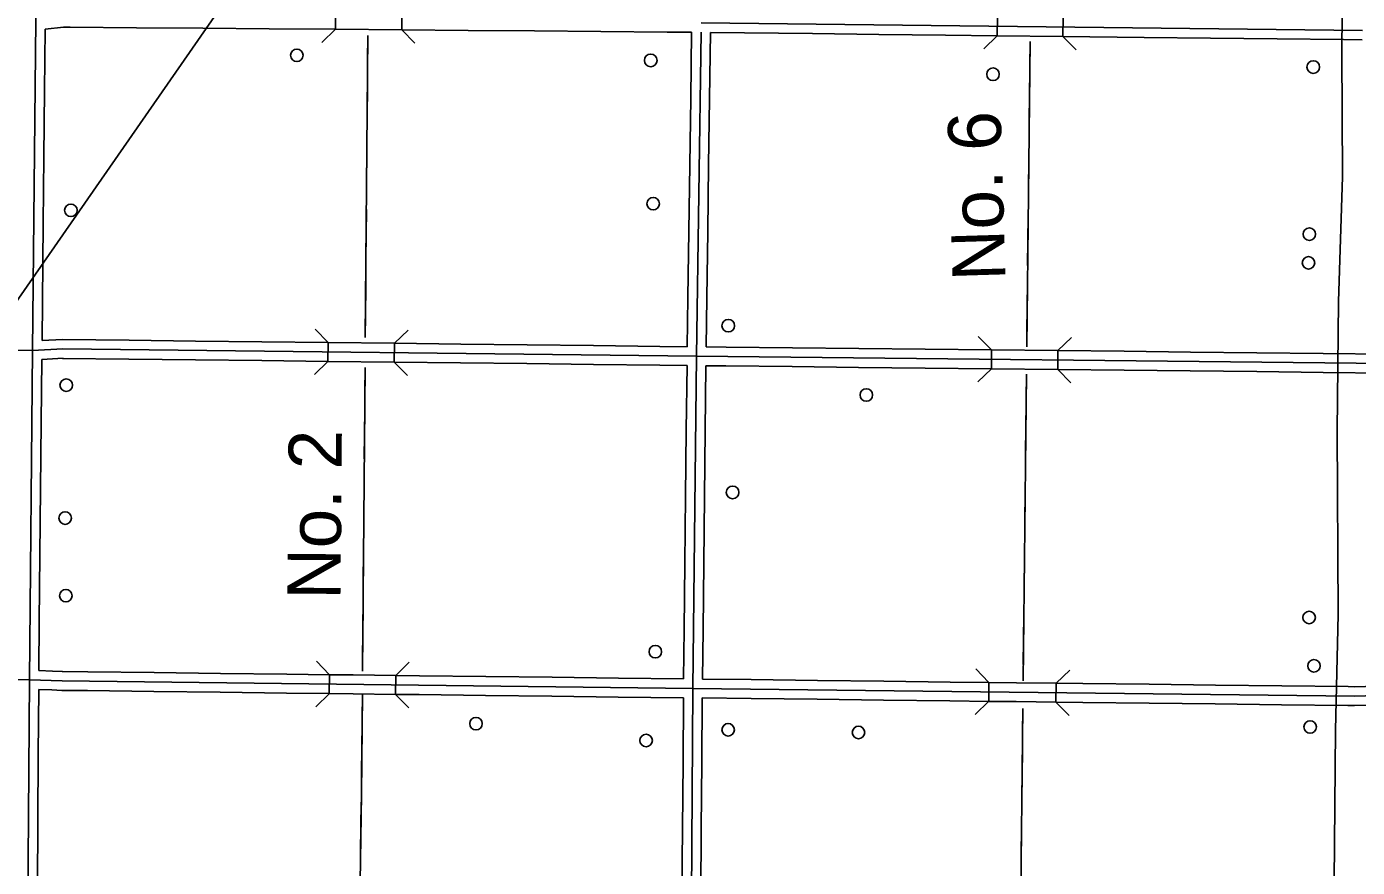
# Model space of a CAD drawing. Extents: x -4306 to 3843, y 131 to 8341.
# Drawn here: x -1949 to -255, y 879 to 1950 of the extents above; entities that cross this region are included whole.
import ezdxf

# ---------------------------------------------------------------- set-up
doc = ezdxf.new("R2010")
doc.units = 0
for name, color, linetype in [('10', 7, 'Continuous'), ('31', 7, 'Continuous'), ('32', 7, 'Continuous'), ('38', 7, 'Continuous'), ('50', 7, 'Continuous'), ('56', 7, 'Continuous'), ('57', 7, 'Continuous')]:
    doc.layers.add(name, color=color, linetype=linetype)

msp = doc.modelspace()

# ---------------------------------------------------------------- linework, layer by layer
at = {"layer": '10'}
msp.add_lwpolyline([(-314.4, 293.8), (-314.5, 305.1), (-312.3, 441.3), (-305.4, 600.9), (-302, 628.3), (-293.8, 664.7), (-283.6, 735.2), (-284.1, 861.9), (-282.2, 1054.1), (-278.9, 1201.3), (-280.3, 1434.8), (-278.7, 1599.9), (-273.4, 1758.6), (-274.2, 1917.6), (-271, 2305.4), (-270.3, 2716.6), (-269.9, 2753.7)], dxfattribs=at)
at = {"layer": '31'}
for p, q in [((-713.1, 1938.1), (-712.8, 1962.1)), ((-629.6, 1937.2), (-629.3, 1961.2)), ((-948.3, 1940.8), (-1078.4, 1942.2)), ((-713.1, 1938.1), (-779.3, 1938.9)), ((-629.6, 1937.2), (-713.1, 1938.1)), ((-525.9, 1936), (-629.6, 1937.2)), ((-441.4, 1935.1), (-525.9, 1936)), ((-356.9, 1934.1), (-441.4, 1935.1)), ((-272.4, 1933.2), (-356.9, 1934.1)), ((-248.5, 1932.9), (-272.4, 1933.2)), ((-1926.5, 1868.2), (-1927.3, 1783.7)), ((-1927.3, 1783.7), (-1928.2, 1699.2)), ((-1929.7, 1549.9), (-1928.2, 1699.2)), ((-1928.2, 1699.2), (-1928.2, 1699.2)), ((-1930, 1525.9), (-1930.7, 1445.7)), ((-1930.7, 1445.7), (-1931.5, 1361.3)), ((-1931.5, 1361.3), (-1931.5, 1361.3)), ((-1933.2, 1192.3), (-1933.8, 1129.8)), ((-1934, 1105.8), (-1934.5, 1023.3))]:
    msp.add_line(p, q, dxfattribs=at)
for points in [[(-1925.7, 1946.5), (-1926.5, 1868.2)], [(-948.3, 1940.8), (-863.8, 1939.8)], [(-863.8, 1939.8), (-779.3, 1938.9)], [(-1932.4, 1276.8), (-1931.5, 1361.3)], [(-1933.2, 1192.3), (-1932.4, 1276.8)], [(-1935.1, 938.9), (-1934.5, 1023.3)], [(-1935.7, 854.4), (-1935.1, 938.9)]]:
    msp.add_lwpolyline(points, dxfattribs=at)
at = {"layer": '32'}
for p, q in [((-1556.1, 1946.2), (-1555.9, 1970.2)), ((-1471.6, 1945.5), (-1471.4, 1969.5)), ((-248.2, 1944.9), (-1090.3, 1954.4)), ((-1925.7, 1946.5), (-1902.6, 1949)), ((-1902.6, 1949), (-1894, 1948.9)), ((-1894, 1948.9), (-1809.6, 1948.3)), ((-1809.6, 1948.3), (-1725.1, 1947.6)), ((-1725.1, 1947.6), (-1640.6, 1946.9)), ((-1640.6, 1946.9), (-1556.1, 1946.2)), ((-1556.1, 1946.2), (-1471.6, 1945.5)), ((-1471.6, 1945.5), (-1387.1, 1944.8)), ((-1387.1, 1944.8), (-1302.6, 1944.1)), ((-1302.6, 1944.1), (-1218.2, 1943.4)), ((-1218.2, 1943.4), (-1133.7, 1942.7)), ((-1133.7, 1942.7), (-1102.6, 1942.5)), ((-1102.4, 1942.7), (-1103.6, 1858.2)), ((-1090.4, 1942.6), (-1096.1, 1530.1)), ((-1078.4, 1942.2), (-1079.6, 1857.9)), ((-1103.6, 1858.2), (-1104.8, 1773.8)), ((-1079.6, 1857.9), (-1080.8, 1773.4)), ((-1104.8, 1773.8), (-1105.9, 1689.3)), ((-1080.8, 1773.4), (-1081.9, 1688.9)), ((-1105.9, 1689.3), (-1107.1, 1604.8)), ((-1081.9, 1688.9), (-1083.1, 1604.5)), ((-1107.1, 1604.8), (-1108, 1542.2)), ((-1083.1, 1604.5), (-1084, 1542)), ((-1929.7, 1549.9), (-1903.6, 1551.4)), ((-1903.6, 1551.4), (-1818.7, 1550.4)), ((-1818.7, 1550.4), (-1734.3, 1549.4)), ((-1734.3, 1549.4), (-1649.8, 1548.4)), ((-1649.8, 1548.4), (-1565.3, 1547.5)), ((-1565.6, 1523.5), (-1565.3, 1547.5)), ((-1565.3, 1547.5), (-1480.8, 1546.5)), ((-1481.1, 1522.5), (-1480.8, 1546.5)), ((-1480.8, 1546.5), (-1396.3, 1545.5)), ((-1396.3, 1545.5), (-1311.8, 1544.6)), ((-1311.8, 1544.6), (-1227.4, 1543.6)), ((-1227.4, 1543.6), (-1142.9, 1542.6)), ((-1142.9, 1542.6), (-1108, 1542.2)), ((-2581.2, 1542), (-1941.9, 1537.3)), ((-1941.9, 1537.3), (-1903.4, 1539.3)), ((-1930, 1525.9), (-1902.7, 1527.4)), ((-1903.5, 1527.3), (-1819, 1526.4)), ((-1903.4, 1539.3), (-1096.1, 1530.1)), ((-1819, 1526.4), (-1734.5, 1525.4)), ((-1734.5, 1525.4), (-1650, 1524.4)), ((-1096.1, 1530.1), (-1100.7, 1107.1)), ((-1096.1, 1530.1), (156, 1516.7)), ((-1084, 1542), (-1058.4, 1541.7)), ((-1058.4, 1541.7), (-973.9, 1540.8)), ((-973.9, 1540.8), (-889.4, 1539.9)), ((-889.4, 1539.9), (-804.9, 1539)), ((-804.9, 1539), (-720.5, 1538.1)), ((-720.7, 1514.1), (-720.5, 1538.1)), ((-720.5, 1538.1), (-636, 1537.2)), ((-636.2, 1513.2), (-636, 1537.2)), ((-636, 1537.2), (-551.5, 1536.3)), ((-551.5, 1536.3), (-467, 1535.4)), ((-467, 1535.4), (-382.5, 1534.4)), ((-382.5, 1534.4), (-298, 1533.5)), ((-298, 1533.5), (-213.6, 1532.6)), ((-1650, 1524.4), (-1565.6, 1523.5)), ((-1565.6, 1523.5), (-1481.1, 1522.5)), ((-1481.1, 1522.5), (-1396.6, 1521.5)), ((-1396.6, 1521.5), (-1312.1, 1520.6)), ((-1312.1, 1520.6), (-1227.6, 1519.6)), ((-1227.6, 1519.6), (-1143.1, 1518.6)), ((-1143.1, 1518.6), (-1108.3, 1518.2)), ((-1108.3, 1518.2), (-1109.2, 1435.8)), ((-1084.3, 1518), (-1085.2, 1435.5)), ((-1084.3, 1518), (-1058.7, 1517.7)), ((-1058.7, 1517.7), (-974.2, 1516.8)), ((-974.2, 1516.8), (-889.7, 1515.9)), ((-889.7, 1515.9), (-805.2, 1515)), ((-805.2, 1515), (-720.7, 1514.1)), ((-720.7, 1514.1), (-636.2, 1513.2)), ((-636.2, 1513.2), (-551.7, 1512.3)), ((-551.7, 1512.3), (-467.3, 1511.4)), ((-467.3, 1511.4), (-382.8, 1510.4)), ((-382.8, 1510.4), (-298.3, 1509.5)), ((-298.3, 1509.5), (-213.8, 1508.6)), ((-1109.2, 1435.8), (-1110.1, 1351.3)), ((-1085.2, 1435.5), (-1086.1, 1351)), ((-1110.1, 1351.3), (-1111, 1266.8)), ((-1086.1, 1351), (-1087, 1266.6)), ((-1111.9, 1182.3), (-1111, 1266.8)), ((-1111.9, 1182.3), (-1111, 1266.8)), ((-1087, 1266.6), (-1087.9, 1182.1)), ((-1111.9, 1182.3), (-1112.6, 1119.3)), ((-1087.9, 1182.1), (-1088.6, 1119)), ((-2592.6, 1124.5), (-1945.9, 1118.2)), ((-1933.8, 1129.8), (-1916.3, 1129.2)), ((-1916.3, 1129.2), (-1903.7, 1128.7)), ((-1871.4, 1128.3), (-1904, 1128.7)), ((-1786.9, 1127.3), (-1871.4, 1128.3)), ((-1702.4, 1126.3), (-1786.9, 1127.3)), ((-1617.9, 1125.3), (-1702.4, 1126.3)), ((-1563.6, 1124.6), (-1617.9, 1125.3)), ((-1563.6, 1124.6), (-1563.9, 1100.6)), ((-1533.5, 1124.3), (-1563.7, 1124.6)), ((-1479.3, 1123.6), (-1533.5, 1124.3)), ((-1479.3, 1123.6), (-1479.6, 1099.6)), ((-1449, 1123.3), (-1479.3, 1123.6)), ((-1364.5, 1122.3), (-1449, 1123.3)), ((-1280, 1121.3), (-1364.5, 1122.3)), ((-1195.5, 1120.2), (-1280, 1121.3)), ((-1112.6, 1119.3), (-1195.5, 1120.2)), ((-1026.6, 1118.3), (-1088.6, 1119)), ((-1945.9, 1118.2), (-1904.1, 1116.7)), ((-1934, 1105.8), (-1917.1, 1105.2)), ((-1917.1, 1105.2), (-1904.5, 1104.7)), ((-1871.7, 1104.3), (-1904.3, 1104.7)), ((-1100.7, 1107.1), (-1904.1, 1116.7)), ((-1787.2, 1103.3), (-1871.7, 1104.3)), ((-1702.7, 1102.3), (-1787.2, 1103.3)), ((-1618.2, 1101.3), (-1702.7, 1102.3)), ((-1100.7, 1107.1), (-1107, 268.2)), ((-258.3, 1097.3), (-1100.7, 1107.1)), ((-942.1, 1117.3), (-1026.6, 1118.3)), ((-857.6, 1116.3), (-942.1, 1117.3)), ((-773.1, 1115.3), (-857.6, 1116.3)), ((-723.7, 1114.7), (-773.1, 1115.3)), ((-723.7, 1114.7), (-724, 1090.7)), ((-688.6, 1114.3), (-723.7, 1114.7)), ((-638.1, 1113.8), (-688.6, 1114.3)), ((-638.1, 1113.8), (-638.4, 1089.7)), ((-604.1, 1113.4), (-638.1, 1113.8)), ((-519.7, 1112.4), (-604.1, 1113.4)), ((-435.2, 1111.4), (-519.7, 1112.4)), ((-350.7, 1110.4), (-435.2, 1111.4)), ((-266.2, 1109.4), (-350.7, 1110.4)), ((-258.4, 1109.3), (-266.2, 1109.4)), ((-182.2, 1111.3), (-258.4, 1109.3)), ((152.6, 1107.8), (-258.3, 1097.3)), ((-1564, 1100.6), (-1618.2, 1101.3)), ((-1533.7, 1100.3), (-1564, 1100.6)), ((-1479.6, 1099.6), (-1533.7, 1100.3)), ((-1449.3, 1099.3), (-1479.6, 1099.6)), ((-1364.8, 1098.3), (-1449.3, 1099.3)), ((-1280.3, 1097.3), (-1364.8, 1098.3)), ((-1195.8, 1096.2), (-1280.3, 1097.3)), ((-1112.8, 1095.3), (-1195.8, 1096.2)), ((-1112.8, 1095.3), (-1113.4, 1013.3)), ((-1088.8, 1095), (-1089.4, 1013.2)), ((-1026.8, 1094.3), (-1088.8, 1095)), ((-942.4, 1093.3), (-1026.8, 1094.3)), ((-857.9, 1092.3), (-942.4, 1093.3)), ((-773.4, 1091.3), (-857.9, 1092.3)), ((-723.9, 1090.7), (-773.4, 1091.3)), ((-688.9, 1090.3), (-724, 1090.7)), ((-638.2, 1089.7), (-688.9, 1090.3)), ((-604.4, 1089.4), (-638.2, 1089.7)), ((-519.9, 1088.4), (-604.4, 1089.4)), ((-435.5, 1087.4), (-519.9, 1088.4)), ((-351, 1086.4), (-435.5, 1087.4)), ((-266.5, 1085.4), (-351, 1086.4)), ((-258.2, 1085.3), (-266.5, 1085.4)), ((-181.6, 1087.3), (-258.2, 1085.3)), ((-1113.4, 1013.3), (-1114.1, 928.8)), ((-1089.4, 1013.2), (-1090.1, 928.7)), ((-1114.1, 928.8), (-1114.7, 844.4)), ((-1090.1, 928.7), (-1090.7, 844.2))]:
    msp.add_line(p, q, dxfattribs=at)
msp.add_lwpolyline([(-1927.2, 3133.3), (-1928.9, 2805.9), (-1937.5, 1957.3), (-1941.9, 1537.3), (-1945.9, 1118.2), (-1949.1, 657.8)], dxfattribs=at)
at = {"layer": '38'}
for p, q in [((-723.9, 1102.8), (-723.9, 1102.8)), ((-638.2, 1101.8), (-638.2, 1101.8))]:
    msp.add_line(p, q, dxfattribs=at)
for points in [[(-1556.1, 1946.2), (-1573.2, 1929.3)], [(-1454.8, 1928.4), (-1471.6, 1945.5)], [(-713.1, 1938.1), (-730.2, 1921.3)], [(-612.8, 1920), (-629.6, 1937.2)], [(-1582.1, 1564.6), (-1565.3, 1547.5)], [(-1480.8, 1546.5), (-1463.6, 1563.3)], [(-737.3, 1555.2), (-720.5, 1538.1)], [(-636, 1537.2), (-618.8, 1554)], [(-1565.6, 1523.5), (-1582.7, 1506.7)], [(-1464.3, 1505.3), (-1481.1, 1522.5)], [(-720.7, 1514.1), (-737.9, 1497.3)], [(-619.4, 1496), (-636.2, 1513.2)], [(-1580.2, 1141.8), (-1563.5, 1124.6)], [(-1479.3, 1123.6), (-1462.1, 1140.4)], [(-723.7, 1114.8), (-740.5, 1132)], [(-620.9, 1130.6), (-638.1, 1113.8)], [(-1563.8, 1100.6), (-1580.9, 1083.9)], [(-1462.8, 1082.5), (-1479.6, 1099.6)], [(-741.2, 1074), (-724, 1090.8)], [(-638.4, 1089.8), (-621.6, 1072.6)]]:
    msp.add_lwpolyline(points, dxfattribs=at)
at = {"layer": '50'}
msp.add_line((-2436.2, 918.6), (-544.5, 3638.5), dxfattribs=at)
at = {"layer": '56'}
for points in [[(-1514.8, 1938.5), (-1518.1, 1554)], [(-1514.8, 1938.5), (-1515.1, 1906.8)], [(-671.4, 1930.7), (-675.6, 1542)], [(-671.4, 1930.7), (-671.8, 1899)], [(-1515.3, 1885.7), (-1515.8, 1822.3)], [(-672, 1877.9), (-672.7, 1814.5)], [(-1516, 1801.2), (-1516.5, 1737.8)], [(-672.9, 1793.4), (-673.6, 1730)], [(-1516.7, 1716.7), (-1517.2, 1653.3)], [(-673.8, 1708.9), (-674.5, 1645.5)], [(-1517.4, 1632.2), (-1517.9, 1568.9)], [(-674.7, 1624.4), (-675.4, 1561.1)], [(-1518.4, 1515.5), (-1521.6, 1129.1)], [(-1518.4, 1515.5), (-1518.6, 1483.8)], [(-676, 1507.4), (-680.3, 1117)], [(-676, 1507.4), (-676.4, 1475.7)], [(-1518.8, 1462.7), (-1519.3, 1399.3)], [(-676.6, 1454.6), (-677.3, 1391.2)], [(-1519.5, 1378.2), (-1520.1, 1314.9)], [(-677.5, 1370.1), (-678.2, 1306.7)], [(-1520.2, 1293.7), (-1520.8, 1230.4)], [(-678.4, 1285.6), (-679.1, 1222.3)], [(-1520.9, 1209.3), (-1521.5, 1145.9)], [(-679.3, 1201.1), (-680, 1137.8)], [(-1521.8, 1099.7), (-1522.9, 972), (-1533.2, 305.2)], [(-1521.8, 1099.7), (-1522.1, 1068)], [(-680.6, 1081.4), (-689.1, 300.9)], [(-680.6, 1081.4), (-681, 1049.7)], [(-1522.3, 1046.9), (-1522.8, 983.5)], [(-681.2, 1028.6), (-681.9, 965.2)], [(-1523.1, 962.4), (-1524, 899.1)], [(-682.1, 944.1), (-682.8, 880.8)]]:
    msp.add_lwpolyline(points, dxfattribs=at)
at = {"layer": '57'}
for centre in [(-1605.2, 1913.1), (-1154.5, 1906.6), (-310.7, 1898.1), (-718.6, 1889), (-1151.4, 1724.2), (-1893, 1715.8), (-315.7, 1685.4), (-316.8, 1648.9), (-1055.8, 1568.9), (-1898.9, 1493.2), (-879.9, 1480.7), (-1050.3, 1356.7), (-1900.3, 1324), (-1899.4, 1225.2), (-316, 1197.4), (-1148.6, 1153.9), (-309.8, 1135.9), (-1377.1, 1062.3), (-1055.9, 1054.5), (-889.9, 1051.1), (-314.7, 1058.1), (-1160.4, 1040.9)]:
    msp.add_circle(centre, 8, dxfattribs=at)

# ---------------------------------------------------------------- texts
at = {"layer": '56'}
for s, rotation, p in [('No. 6', 91.7362, (-702.5, 1626.9)), ('No. 2', 89.5125, (-1549.7, 1220))]:
    msp.add_text(s, height=67.59, rotation=rotation, dxfattribs=at).set_placement(p)

doc.saveas('drawing.dxf')
